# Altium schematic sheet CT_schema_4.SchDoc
size 298 x 247 mm
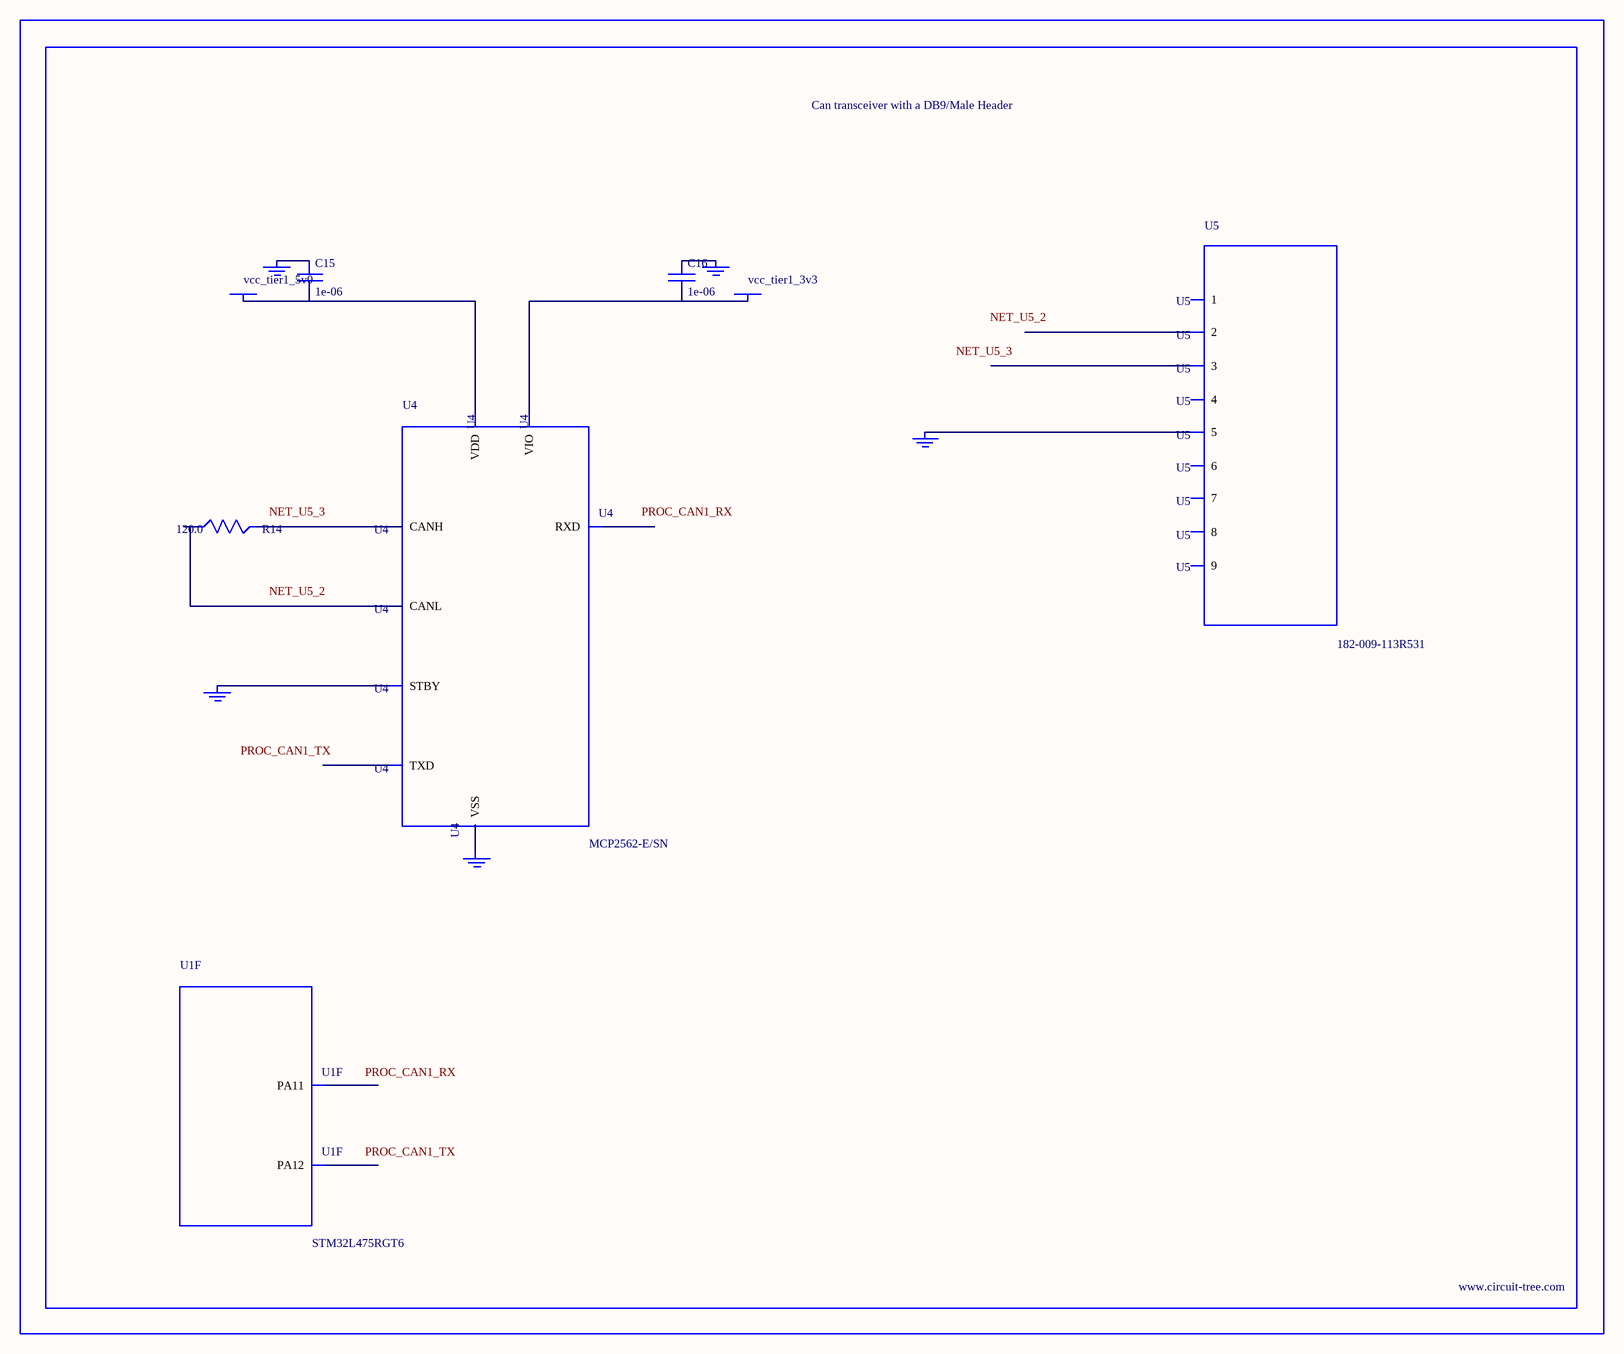
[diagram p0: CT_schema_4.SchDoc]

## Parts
BORDER3  (no value)
C15  1e-06  [C0603]
C16  1e-06  [C0603]
GND_INSTANCE_3_0  (no value)
GND_INSTANCE_3_1  (no value)
GND_INSTANCE_3_2  (no value)
GND_INSTANCE_3_3  (no value)
GND_INSTANCE_3_4  (no value)
POWER_INSTANCE_3_0  vcc_tier1_5v0
POWER_INSTANCE_3_1  vcc_tier1_3v3
R14  120.0  [R0603]
U1  STM32L475RGT6  [LQFP64]  (part F of 8)
U4  MCP2562-E/SN  [SOIC-8]
U5  182-009-113R531  [182-009-MALE]

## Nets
NetC15_1: C15.1 GND_INSTANCE_3_0.0(GND)
NetC15_2: C15.2 POWER_INSTANCE_3_0.0(PWR) U4.3(VDD)
NetC16_1: C16.1 GND_INSTANCE_3_1.0(GND)
NetC16_2: C16.2 POWER_INSTANCE_3_1.0(PWR) U4.5(VIO)
NetGND_INSTANCE_3_2_0: GND_INSTANCE_3_2.0(GND) U4.8(STBY)
NetGND_INSTANCE_3_3_0: GND_INSTANCE_3_3.0(GND) U4.2(VSS)
NetGND_INSTANCE_3_4_0: GND_INSTANCE_3_4.0(GND) U5.5
NetR14_1: R14.1 U4.6(CANL)
NetR14_2: R14.2 U4.7(CANH)

Not connected (* = marked no-connect by the designer): U1 44(PA11) 45(PA12); U4 1(TXD) 4(RXD); U5 1 2 3 4 6 7 8 9

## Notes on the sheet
- Labels drawn without touching a wire or pin: NET_U5_2, NET_U5_3, PROC_CAN1_RX, PROC_CAN1_TX

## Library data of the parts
BORDER3 = BORDER_PAGE3
C15 C16 = C0603C105K3RACTU
GND_INSTANCE_3_0-GND_INSTANCE_3_4 = GND
POWER_INSTANCE_3_0 POWER_INSTANCE_3_1 = PWR
R14 = RC0603JR-07120RL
